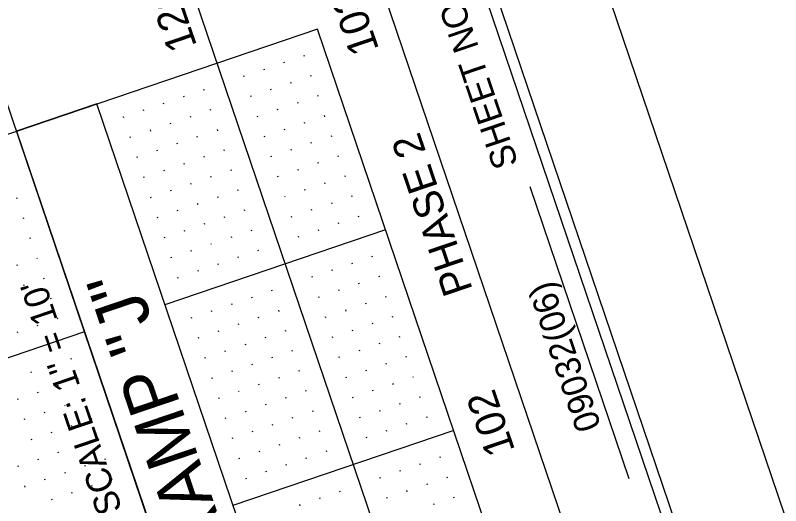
# Model space of a CAD drawing. Extents: x 2150318 to 2152065, y 143281 to 145371.
# Drawn here: x 2151290.7 to 2151471.2, y 145139 to 145254.7 of the extents above; entities that cross this region are included whole.
import ezdxf

# ---------------------------------------------------------------- set-up
doc = ezdxf.new("R2010")
doc.units = 0
for name, color, linetype in [('PR_Align_Ramp_J_Sta', 7, 'Continuous'), ('SHT_Plan_Profile_Sheet_Elev_Txt', 7, 'Continuous'), ('SHT_Plan_Profile_Sheet_Sta_Txt', 7, 'Continuous'), ('SHT_Plan_Profile_Sheet_Txt', 7, 'Continuous'), ('SHT_Plot_Shape_Half', 7, 'Continuous'), ('SHT_Profile_Grid_Major', 7, 'Continuous'), ('SHT_Profile_Grid_Minor', 7, 'Continuous'), ('SHT_Scale', 7, 'Continuous'), ('SHT_Sheet_Border', 7, 'Continuous'), ('SHT_Standard_Sheet_Lines', 7, 'Continuous')]:
    doc.layers.add(name, color=color, linetype=linetype)

msp = doc.modelspace()

# ---------------------------------------------------------------- linework, layer by layer
at = {"layer": 'SHT_Plot_Shape_Half'}
msp.add_lwpolyline([(2150909.49, 143371.4), (2150363.35, 144981.29), (2151405.04, 145334.68), (2151951.18, 143724.79)], close=True, dxfattribs=at)
at = {"layer": 'SHT_Profile_Grid_Major'}
for p, q in [((2151832.26, 143787.41), (2151326.27, 145278.92)), ((2151784.91, 143771.34), (2151278.93, 145262.85)), ((2151378.06, 145204.09), (2151325.98, 145186.42)), ((2151307.04, 145179.99), (2150928.24, 145051.49)), ((2151394.12, 145156.74), (2151342.04, 145139.07))]:
    msp.add_line(p, q, dxfattribs=at)
at = {"layer": 'SHT_Profile_Grid_Minor'}
for p, q in [((2151358.91, 145244.98), (2151358.83, 145245.21)), ((2151354.17, 145243.37), (2151354.09, 145243.61)), ((2151344.7, 145240.16), (2151344.62, 145240.39)), ((2151349.44, 145241.76), (2151349.36, 145242)), ((2151360.51, 145240.24), (2151360.43, 145240.48)), ((2151355.78, 145238.63), (2151355.7, 145238.87)), ((2151335.23, 145236.94), (2151335.15, 145237.18)), ((2151351.04, 145237.03), (2151350.96, 145237.27)), ((2151330.5, 145235.34), (2151330.42, 145235.57)), ((2151346.31, 145235.42), (2151346.23, 145235.66)), ((2151362.12, 145235.51), (2151362.04, 145235.74)), ((2151325.76, 145233.73), (2151325.68, 145233.97)), ((2151357.39, 145233.9), (2151357.31, 145234.14)), ((2151321.03, 145232.13), (2151320.95, 145232.36)), ((2151336.84, 145232.21), (2151336.76, 145232.45)), ((2151352.65, 145232.29), (2151352.57, 145232.53)), ((2151316.29, 145230.52), (2151316.21, 145230.76)), ((2151332.1, 145230.6), (2151332.02, 145230.84)), ((2151347.92, 145230.69), (2151347.84, 145230.92)), ((2151363.73, 145230.77), (2151363.65, 145231.01)), ((2151327.37, 145229), (2151327.29, 145229.23)), ((2151338.45, 145227.47), (2151338.37, 145227.71)), ((2151354.26, 145227.56), (2151354.18, 145227.8)), ((2151358.99, 145229.16), (2151358.91, 145229.4)), ((2151317.9, 145225.78), (2151317.82, 145226.02)), ((2151322.63, 145227.39), (2151322.55, 145227.63)), ((2151333.71, 145225.87), (2151333.63, 145226.11)), ((2151349.52, 145225.95), (2151349.44, 145226.19)), ((2151365.33, 145226.04), (2151365.25, 145226.27)), ((2151328.98, 145224.26), (2151328.9, 145224.5)), ((2151360.6, 145224.43), (2151360.52, 145224.67)), ((2151324.24, 145222.66), (2151324.16, 145222.89)), ((2151340.05, 145222.74), (2151339.97, 145222.98)), ((2151355.86, 145222.82), (2151355.78, 145223.06)), ((2151319.51, 145221.05), (2151319.43, 145221.29)), ((2151335.32, 145221.13), (2151335.24, 145221.37)), ((2151351.13, 145221.22), (2151351.05, 145221.45)), ((2151366.94, 145221.3), (2151366.86, 145221.54)), ((2151330.58, 145219.53), (2151330.5, 145219.76)), ((2151362.2, 145219.7), (2151362.12, 145219.93)), ((2151325.85, 145217.92), (2151325.77, 145218.16)), ((2151341.66, 145218), (2151341.58, 145218.24)), ((2151357.47, 145218.09), (2151357.39, 145218.33)), ((2151321.11, 145216.31), (2151321.03, 145216.55)), ((2151336.92, 145216.4), (2151336.84, 145216.64)), ((2151352.73, 145216.48), (2151352.65, 145216.72)), ((2151363.81, 145214.96), (2151363.73, 145215.2)), ((2151368.55, 145216.57), (2151368.47, 145216.8)), ((2151327.45, 145213.19), (2151327.37, 145213.42)), ((2151332.19, 145214.79), (2151332.11, 145215.03)), ((2151343.26, 145213.27), (2151343.18, 145213.51)), ((2151359.08, 145213.35), (2151359, 145213.59)), ((2151291.1, 145211.41), (2151291.02, 145211.65)), ((2151322.72, 145211.58), (2151322.64, 145211.82)), ((2151338.53, 145211.66), (2151338.45, 145211.9)), ((2151354.34, 145211.75), (2151354.26, 145211.98)), ((2151370.15, 145211.83), (2151370.07, 145212.07)), ((2151333.8, 145210.06), (2151333.71, 145210.29)), ((2151365.42, 145210.23), (2151365.34, 145210.46)), ((2151329.06, 145208.45), (2151328.98, 145208.69)), ((2151344.87, 145208.53), (2151344.79, 145208.77)), ((2151360.68, 145208.62), (2151360.6, 145208.86)), ((2151292.7, 145206.68), (2151292.62, 145206.91)), ((2151324.33, 145206.84), (2151324.24, 145207.08)), ((2151340.14, 145206.93), (2151340.06, 145207.17)), ((2151355.95, 145207.01), (2151355.87, 145207.25)), ((2151371.76, 145207.1), (2151371.68, 145207.33)), ((2151335.4, 145205.32), (2151335.32, 145205.56)), ((2151367.02, 145205.49), (2151366.94, 145205.73)), ((2151330.67, 145203.72), (2151330.59, 145203.95)), ((2151341.74, 145202.19), (2151341.66, 145202.43)), ((2151346.48, 145203.8), (2151346.4, 145204.04)), ((2151357.55, 145202.28), (2151357.47, 145202.51)), ((2151362.29, 145203.88), (2151362.21, 145204.12)), ((2151294.31, 145201.94), (2151294.23, 145202.18)), ((2151325.93, 145202.11), (2151325.85, 145202.35)), ((2151337.01, 145200.59), (2151336.93, 145200.82)), ((2151332.27, 145198.98), (2151332.19, 145199.22)), ((2151348.08, 145199.07), (2151348, 145199.3)), ((2151295.92, 145197.21), (2151295.84, 145197.44)), ((2151327.54, 145197.37), (2151327.46, 145197.61)), ((2151343.35, 145197.46), (2151343.27, 145197.7)), ((2151374.97, 145197.63), (2151374.89, 145197.86)), ((2151291.18, 145195.6), (2151291.1, 145195.84)), ((2151338.61, 145195.85), (2151338.53, 145196.09)), ((2151370.24, 145196.02), (2151370.16, 145196.26)), ((2151333.88, 145194.25), (2151333.8, 145194.48)), ((2151365.5, 145194.41), (2151365.42, 145194.65)), ((2151297.52, 145192.47), (2151297.44, 145192.71)), ((2151329.14, 145192.64), (2151329.06, 145192.88)), ((2151360.77, 145192.81), (2151360.69, 145193.04)), ((2151376.58, 145192.89), (2151376.5, 145193.13)), ((2151292.79, 145190.87), (2151292.71, 145191.1)), ((2151351.3, 145189.6), (2151351.22, 145189.83)), ((2151367.11, 145189.68), (2151367.03, 145189.92)), ((2151371.84, 145191.29), (2151371.76, 145191.52)), ((2151299.13, 145187.74), (2151299.05, 145187.97)), ((2151346.56, 145187.99), (2151346.48, 145188.23)), ((2151362.37, 145188.07), (2151362.29, 145188.31)), ((2151378.18, 145188.16), (2151378.1, 145188.39)), ((2151294.39, 145186.13), (2151294.31, 145186.37)), ((2151341.83, 145186.38), (2151341.75, 145186.62)), ((2151373.45, 145186.55), (2151373.37, 145186.79)), ((2151337.09, 145184.78), (2151337.01, 145185.01)), ((2151352.9, 145184.86), (2151352.82, 145185.1)), ((2151368.71, 145184.94), (2151368.63, 145185.18)), ((2151300.73, 145183), (2151300.65, 145183.24)), ((2151332.36, 145183.17), (2151332.28, 145183.41)), ((2151348.17, 145183.25), (2151348.09, 145183.49)), ((2151363.98, 145183.34), (2151363.9, 145183.57)), ((2151379.79, 145183.42), (2151379.71, 145183.66)), ((2151296, 145181.4), (2151295.92, 145181.63)), ((2151343.43, 145181.65), (2151343.35, 145181.88)), ((2151375.06, 145181.82), (2151374.98, 145182.05)), ((2151291.26, 145179.79), (2151291.18, 145180.03)), ((2151338.7, 145180.04), (2151338.62, 145180.28)), ((2151354.51, 145180.13), (2151354.43, 145180.36)), ((2151370.32, 145180.21), (2151370.24, 145180.45)), ((2151333.96, 145178.43), (2151333.88, 145178.67)), ((2151345.04, 145176.91), (2151344.96, 145177.15)), ((2151349.77, 145178.52), (2151349.69, 145178.76)), ((2151365.59, 145178.6), (2151365.51, 145178.84)), ((2151376.66, 145177.08), (2151376.58, 145177.32)), ((2151381.4, 145178.69), (2151381.32, 145178.92)), ((2151340.3, 145175.31), (2151340.22, 145175.54)), ((2151356.12, 145175.39), (2151356.04, 145175.63)), ((2151371.93, 145175.47), (2151371.85, 145175.71)), ((2151303.95, 145173.53), (2151303.87, 145173.77)), ((2151335.57, 145173.7), (2151335.49, 145173.94)), ((2151351.38, 145173.78), (2151351.3, 145174.02)), ((2151367.19, 145173.87), (2151367.11, 145174.1)), ((2151383, 145173.95), (2151382.92, 145174.19)), ((2151299.21, 145171.93), (2151299.13, 145172.16)), ((2151346.65, 145172.18), (2151346.57, 145172.41)), ((2151378.27, 145172.35), (2151378.19, 145172.58)), ((2151294.48, 145170.32), (2151294.4, 145170.56)), ((2151341.91, 145170.57), (2151341.83, 145170.81)), ((2151357.72, 145170.66), (2151357.64, 145170.89)), ((2151373.53, 145170.74), (2151373.45, 145170.98)), ((2151305.55, 145168.8), (2151305.47, 145169.03)), ((2151337.18, 145168.96), (2151337.1, 145169.2)), ((2151352.99, 145169.05), (2151352.91, 145169.29)), ((2151368.8, 145169.13), (2151368.72, 145169.37)), ((2151384.61, 145169.22), (2151384.53, 145169.45)), ((2151300.82, 145167.19), (2151300.74, 145167.43)), ((2151348.25, 145167.44), (2151348.17, 145167.68)), ((2151379.87, 145167.61), (2151379.79, 145167.85)), ((2151296.08, 145165.58), (2151296, 145165.82)), ((2151343.52, 145165.84), (2151343.44, 145166.07)), ((2151354.59, 145164.31), (2151354.51, 145164.55)), ((2151359.33, 145165.92), (2151359.25, 145166.16)), ((2151370.4, 145164.4), (2151370.32, 145164.63)), ((2151375.14, 145166), (2151375.06, 145166.24)), ((2151386.22, 145164.48), (2151386.14, 145164.72)), ((2151291.35, 145163.98), (2151291.27, 145164.21)), ((2151302.42, 145162.46), (2151302.34, 145162.69)), ((2151307.16, 145164.06), (2151307.08, 145164.3)), ((2151338.78, 145164.23), (2151338.7, 145164.47)), ((2151349.86, 145162.71), (2151349.78, 145162.94)), ((2151381.48, 145162.88), (2151381.4, 145163.11)), ((2151297.69, 145160.85), (2151297.61, 145161.09)), ((2151345.12, 145161.1), (2151345.04, 145161.34)), ((2151360.93, 145161.19), (2151360.85, 145161.42)), ((2151376.75, 145161.27), (2151376.67, 145161.51)), ((2151292.95, 145159.24), (2151292.87, 145159.48)), ((2151308.77, 145159.33), (2151308.69, 145159.56)), ((2151340.39, 145159.5), (2151340.31, 145159.73)), ((2151356.2, 145159.58), (2151356.12, 145159.82)), ((2151372.01, 145159.66), (2151371.93, 145159.9)), ((2151387.82, 145159.75), (2151387.74, 145159.98)), ((2151304.03, 145157.72), (2151303.95, 145157.96)), ((2151351.46, 145157.97), (2151351.38, 145158.21)), ((2151383.09, 145158.14), (2151383.01, 145158.38)), ((2151299.3, 145156.11), (2151299.22, 145156.35)), ((2151346.73, 145156.37), (2151346.65, 145156.6)), ((2151362.54, 145156.45), (2151362.46, 145156.69)), ((2151378.35, 145156.53), (2151378.27, 145156.77)), ((2151294.56, 145154.51), (2151294.48, 145154.74)), ((2151310.37, 145154.59), (2151310.29, 145154.83)), ((2151341.99, 145154.76), (2151341.91, 145155)), ((2151357.81, 145154.84), (2151357.73, 145155.08)), ((2151373.62, 145154.93), (2151373.54, 145155.16)), ((2151305.64, 145152.99), (2151305.56, 145153.22)), ((2151348.34, 145151.63), (2151348.26, 145151.87)), ((2151353.07, 145153.24), (2151352.99, 145153.47)), ((2151364.15, 145151.72), (2151364.07, 145151.95)), ((2151300.9, 145151.38), (2151300.82, 145151.62)), ((2151311.98, 145149.86), (2151311.9, 145150.09)), ((2151343.6, 145150.03), (2151343.52, 145150.26)), ((2151359.41, 145150.11), (2151359.33, 145150.35)), ((2151391.03, 145150.28), (2151390.95, 145150.51)), ((2151291.43, 145148.17), (2151291.35, 145148.4)), ((2151296.17, 145149.77), (2151296.09, 145150.01)), ((2151307.24, 145148.25), (2151307.16, 145148.49)), ((2151354.68, 145148.5), (2151354.6, 145148.74)), ((2151386.3, 145148.67), (2151386.22, 145148.91)), ((2151302.51, 145146.64), (2151302.43, 145146.88)), ((2151349.94, 145146.9), (2151349.86, 145147.13)), ((2151381.56, 145147.06), (2151381.48, 145147.3)), ((2151297.77, 145145.04), (2151297.69, 145145.27)), ((2151313.58, 145145.12), (2151313.5, 145145.36)), ((2151345.21, 145145.29), (2151345.13, 145145.53)), ((2151376.83, 145145.46), (2151376.75, 145145.69)), ((2151392.64, 145145.54), (2151392.56, 145145.78)), ((2151293.04, 145143.43), (2151292.96, 145143.67)), ((2151308.85, 145143.52), (2151308.77, 145143.75)), ((2151387.91, 145143.94), (2151387.83, 145144.17)), ((2151304.12, 145141.91), (2151304.03, 145142.15)), ((2151367.36, 145142.25), (2151367.28, 145142.48)), ((2151383.17, 145142.33), (2151383.09, 145142.57)), ((2151394.25, 145140.81), (2151394.17, 145141.04)), ((2151299.38, 145140.3), (2151299.3, 145140.54)), ((2151315.19, 145140.39), (2151315.11, 145140.62)), ((2151357.89, 145139.03), (2151357.81, 145139.27)), ((2151362.62, 145140.64), (2151362.54, 145140.88)), ((2151378.44, 145140.72), (2151378.36, 145140.96)), ((2151389.51, 145139.2), (2151389.43, 145139.44))]:
    msp.add_line(p, q, dxfattribs=at)
at = {"layer": 'SHT_Sheet_Border'}
msp.add_line((2151362, 145251.44), (2150912.18, 145098.84), dxfattribs=at)
for points in [[(2150901.85, 143471.77), (2150395.86, 144963.28), (2151390.2, 145300.6), (2151896.19, 143809.09)], [(2151445.23, 145060.56), (2151466.54, 145067.79), (2151388.63, 145297.43), (2151367.32, 145290.2)], [(2151339.16, 145085.29), (2151358.1, 145091.72), (2151309.91, 145233.77), (2151290.97, 145227.34)]]:
    msp.add_lwpolyline(points, close=True, dxfattribs=at)
msp.add_lwpolyline([(2151457.96, 145046.39), (2151434.28, 145038.36), (2151362, 145251.44)], dxfattribs=at)
at = {"layer": 'SHT_Standard_Sheet_Lines'}
msp.add_line((2151435.54, 145145.36), (2151412.18, 145214.21), dxfattribs=at)

# ---------------------------------------------------------------- texts
at = {"layer": 'PR_Align_Ramp_J_Sta'}
msp.add_text('RAMP "J"', height=12, rotation=108.7393, dxfattribs=at).set_placement((2151341.18, 145129.15))
at = {"layer": 'SHT_Plan_Profile_Sheet_Elev_Txt'}
msp.add_text('1260', height=7, rotation=108.7393, dxfattribs=at).set_placement((2151333.6, 145247.5))
at = {"layer": 'SHT_Plan_Profile_Sheet_Sta_Txt'}
for s, p in [('103', (2151376.55, 145246.68)), ('102', (2151408.63, 145152.11))]:
    msp.add_text(s, height=7, rotation=108.7393, dxfattribs=at).set_placement(p)
at = {"layer": 'SHT_Plan_Profile_Sheet_Txt'}
for s, height, p in [('SHEET NO.', 6, (2151409.4, 145219.69)), ('PHASE 2', 7, (2151398.65, 145189.99)), ('09032(06)', 6, (2151428.96, 145157.72))]:
    msp.add_text(s, height=height, rotation=108.7393, dxfattribs=at).set_placement(p)
at = {"layer": 'SHT_Scale'}
msp.add_text('VERT. SCALE: 1" = 10\'', height=6, rotation=108.7393, dxfattribs=at).set_placement((2151324.27, 145113.62))

doc.saveas('drawing.dxf')
